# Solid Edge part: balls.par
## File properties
Title: Bearing
Author: vicky raina
Template: Normal.par
Last saved by: Robert a Rhodes jr
Revision: 7
Application: Solid Edge
Material: aluminum
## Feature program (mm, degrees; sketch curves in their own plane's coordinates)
sketch for "unnamed RevolvedProtrusion 1" plane through (0, 0, 0) normal (0, -1, 0) x-axis (1, 0, 0)
  arc centre (0, 0) radius 6.604 from (0, 6.604) to (0, -6.604) cw
  line (0, 6.604) -> (0, -6.604)
  dimension (radial) = 0
revolve "unnamed RevolvedProtrusion 1" add full turn 360 deg
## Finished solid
Body 1: solid body, 1 face, 0 edges, 0 vertices.
  Faces by surface: sphere 1
Spherical faces by radius (mm): R6.604 x1
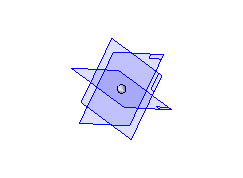
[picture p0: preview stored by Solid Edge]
